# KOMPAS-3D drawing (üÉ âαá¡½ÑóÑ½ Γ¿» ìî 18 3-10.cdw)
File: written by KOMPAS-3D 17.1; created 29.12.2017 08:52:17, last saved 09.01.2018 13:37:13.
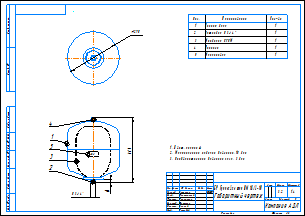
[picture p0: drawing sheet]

Sheet 1: A3, landscape, title-block layout from C:\Лощинин\GRAPHIC.LYT style 1

Title block, sheet 1: name: БР Гранлевел тип НМ 18/3-10 / Габаритный чертеж; mass: 3,2; sheets: 1; sheet format: A3; stored path: K:\АП\20_PKO\02_Насосное направление\Разработка\04_Проекты разные\Баки\КД действующая\Баки Flexcon R\Компас\Чертежи\БР Гранлевел тип НМ 18 1,5-6.cdw; drawn by: Лощинин; checked by: Хантимеров; drawn by, date: 29.12.2017

Views: Вид 1, Снизу, Проекционный вид 2
Referenced files in \\Fsk1\files\АП\20_PKO\02_Насосное направление\Разработка\04_Проекты разные\Баки\КД действующая\Баки Flexcon R\Компас\: 18 литров.a3d
Referenced files in C:\Лощинин\: GRAPHIC.LYT
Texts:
  IvAn
  ADL
  БР Гранлевел тип НМ 18/1,5-6
  АДЛ
  Цвет: красный
  Максимальное рабочее давление: 10 бар
  Предварительное давление газа: 3 бар
  ACAD_ISO03W100_RGB_223_127_255_SC_0.063_THICK_0.05
  ACAD_ISO03W100_RGB_223_127_255_SC_1_THICK_0.05
  Лит-Масса-Масштаб
  Материал-Предприятие
  Масштаб
  Изм.
  Лист
  № докум.
  Подп.
  Дата
  Лит.
  Разраб.
  Пров.
  Т.контр.
  Курлыкина
  Листов
  Нач.отд.
  Щетинин
  Н.контр.
  Долгов
  Утв.
  Рашидов
  Компания АДЛ
  Изменение
  Номер документа
  Подпись
  Обозначение документа
  Наименование изделия
  Масса изделия по ГОСТ 2.109-73
  Порядковый номер листа
  Общее количество листов в документе
  Характер работы, выполненной лицом, подписавшим документ
  Наименование или индекс предприятия, выпускающего документ
  Инв. № подл.
  Подп. и дата
  Взам. инв. №
  Инв. № дубл.
  Инвентарный номер подлинника по ГОСТ 2.501-68
  Подпись принявшего подлинник в отдел технической документации
  Инвентарный номер подлинника, взамен которого выпущен данный подлинник
  Инвентарный номер дубликата по ГОСТ 2.502-68
  Подпись принявшего дубликат в отдел технической документации
  Справ. №
  Перв. примен.
  Обозначение документа, взамен или на основании которого выпущен данный документ
  Обозначение документа, в котором впервые записан данный документ
  Подпись лица, копировавшего чертеж
  Обозначение формата листа
Dimensions and other numbers on the sheet: 290; 357; 16; 4; 5; 1; 3; 2; 1:4; 3,2; 29.12.2017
